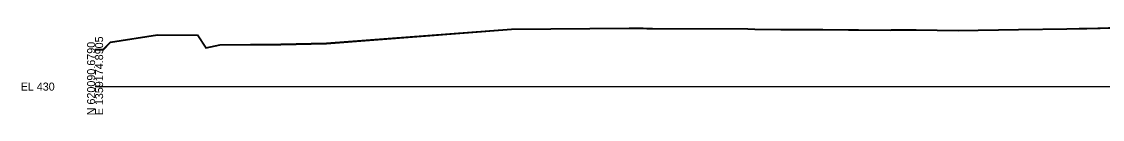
# Model space of a CAD drawing. Extents: x -26 to 803, y -27 to 3586.
# Drawn here: x -25.7 to 352.2, y 1490.3 to 1520.9 of the extents above; entities that cross this region are included whole.
import ezdxf

# ---------------------------------------------------------------- set-up
doc = ezdxf.new("R2010")
doc.units = 0
for name, color, linetype in [('DESIGN - SHEET - Light Grid', 7, 'Continuous'), ('SURVEY - GROUND - Bottom of Topsoil Layer', 7, 'Continuous'), ('SURVEY - GROUND - Top of Ground', 7, 'Continuous')]:
    doc.layers.add(name, color=color, linetype=linetype)

msp = doc.modelspace()

# ---------------------------------------------------------------- linework, layer by layer
at = {"layer": 'DESIGN - SHEET - Light Grid'}
msp.add_line((0, 1500), (400, 1500), dxfattribs=at)
at = {"layer": 'SURVEY - GROUND - Bottom of Topsoil Layer'}
for p, q in [((80.95, 1514.95), (145.59, 1519.91)), ((145.59, 1519.91), (186.73, 1520.22)), ((186.73, 1520.22), (191.62, 1520.24)), ((191.62, 1520.24), (192.91, 1520.14)), ((192.91, 1520.14), (194.9, 1520.14)), ((194.9, 1520.14), (228.21, 1520.02)), ((228.21, 1520.02), (230.72, 1519.89)), ((230.72, 1519.89), (239.75, 1519.82)), ((239.75, 1519.82), (254.53, 1519.73)), ((254.53, 1519.73), (263.48, 1519.65)), ((263.48, 1519.65), (265.07, 1519.64)), ((265.07, 1519.64), (266.9, 1519.61)), ((266.9, 1519.61), (278.11, 1519.58)), ((278.11, 1519.58), (278.49, 1519.61)), ((278.49, 1519.61), (287.08, 1519.63)), ((287.08, 1519.63), (301.79, 1519.46)), ((301.79, 1519.46), (322.89, 1519.76)), ((322.89, 1519.76), (339.83, 1519.97)), ((339.83, 1519.97), (344.09, 1520.09)), ((344.09, 1520.09), (346.84, 1520.12)), ((346.84, 1520.12), (365.76, 1520.66)), ((5.4, 1515.33), (21.87, 1517.9)), ((21.87, 1517.9), (35.82, 1517.75)), ((35.82, 1517.75), (38.72, 1513.4)), ((0, 1512.81), (2.8, 1512.74)), ((2.8, 1512.74), (5.4, 1515.33)), ((38.72, 1513.4), (43.6, 1514.46)), ((43.6, 1514.46), (64.91, 1514.6)), ((64.91, 1514.6), (80.95, 1514.95))]:
    msp.add_line(p, q, dxfattribs=at)
at = {"layer": 'SURVEY - GROUND - Top of Ground'}
msp.add_lwpolyline([(0, 1513.06), (2.8, 1512.99), (5.4, 1515.58), (21.87, 1518.15), (35.82, 1518), (38.72, 1513.65), (43.6, 1514.71), (64.91, 1514.85), (80.95, 1515.2), (145.59, 1520.16), (186.73, 1520.47), (191.62, 1520.49), (192.91, 1520.39), (194.9, 1520.39), (228.21, 1520.27), (230.72, 1520.14), (239.75, 1520.07), (254.53, 1519.98), (263.48, 1519.9), (265.07, 1519.89), (266.9, 1519.86), (278.11, 1519.83), (278.49, 1519.86), (287.08, 1519.88), (301.79, 1519.71), (322.89, 1520.01), (339.83, 1520.22), (344.09, 1520.34), (346.84, 1520.37), (365.76, 1520.91)], dxfattribs=at)

# ---------------------------------------------------------------- texts
at = {"layer": 'DESIGN - SHEET - Light Grid'}
for s, p in [('E 1359174.8905', (2.8, 1490)), ('N 620090.6790', (0, 1490))]:
    msp.add_text(s, height=2.8, rotation=90, dxfattribs=at).set_placement(p)
msp.add_text('EL 430', height=2.8, dxfattribs=at).set_placement((-26, 1498.6))

doc.saveas('drawing.dxf')
